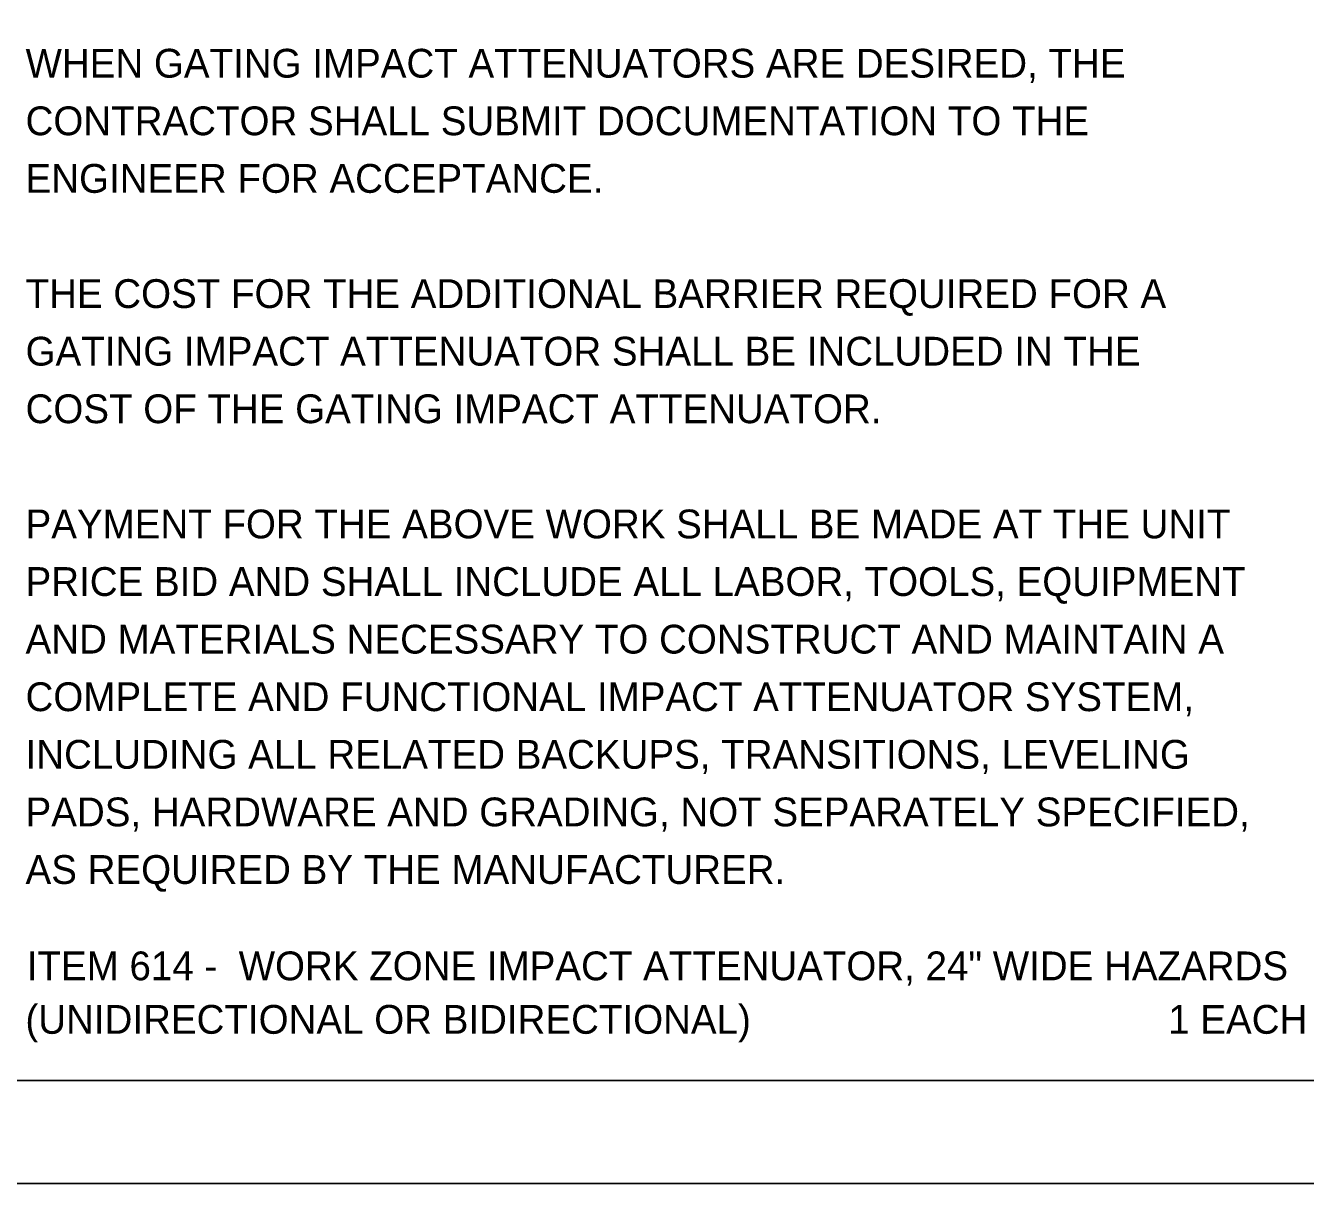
# Model space of a CAD drawing. Extents: x 0 to 34, y 0 to 22.
# Drawn here: x 24.66 to 30.88, y 0 to 5.63 of the extents above; entities that cross this region are included whole.
import ezdxf

# ---------------------------------------------------------------- set-up
doc = ezdxf.new("R2010")
doc.units = 0
for name, color, linetype in [('SH_Border', 7, 'Continuous'), ('SH_Cut_Line', 7, 'Continuous'), ('SH_Text', 7, 'Continuous')]:
    doc.layers.add(name, color=color, linetype=linetype)

msp = doc.modelspace()

# ---------------------------------------------------------------- linework, layer by layer
at = {"layer": 'SH_Border'}
msp.add_lwpolyline([(1.5, 21.5), (33.5, 21.5), (33.5, 0.5), (1.5, 0.5)], close=True, dxfattribs=at)
at = {"layer": 'SH_Cut_Line'}
msp.add_lwpolyline([(0, 0), (34, 0), (34, 22), (0, 22)], close=True, dxfattribs=at)

# ---------------------------------------------------------------- texts
at = {"layer": 'SH_Text'}
for s, p in [('WHEN GATING IMPACT ATTENUATORS ARE DESIRED, THE', (24.66, 5.3761)), ('CONTRACTOR SHALL SUBMIT DOCUMENTATION TO THE', (24.66, 5.0961)), ('ENGINEER FOR ACCEPTANCE.', (24.66, 4.8161)), ('THE COST FOR THE ADDITIONAL BARRIER REQUIRED FOR A', (24.66, 4.2561)), ('GATING IMPACT ATTENUATOR SHALL BE INCLUDED IN THE', (24.66, 3.9761)), ('COST OF THE GATING IMPACT ATTENUATOR.', (24.66, 3.6961)), ('PAYMENT FOR THE ABOVE WORK SHALL BE MADE AT THE UNIT', (24.66, 3.1361)), ('PRICE BID AND SHALL INCLUDE ALL LABOR, TOOLS, EQUIPMENT', (24.66, 2.8561)), ('AND MATERIALS NECESSARY TO CONSTRUCT AND MAINTAIN A', (24.66, 2.5761)), ('COMPLETE AND FUNCTIONAL IMPACT ATTENUATOR SYSTEM,', (24.66, 2.2961)), ('INCLUDING ALL RELATED BACKUPS, TRANSITIONS, LEVELING', (24.66, 2.0161)), ('PADS, HARDWARE AND GRADING, NOT SEPARATELY SPECIFIED,', (24.66, 1.7361)), ('AS REQUIRED BY THE MANUFACTURER.', (24.66, 1.4561)), ('ITEM 614 -  WORK ZONE IMPACT ATTENUATOR, 24" WIDE HAZARDS', (24.6659, 0.9876)), ('(UNIDIRECTIONAL OR BIDIRECTIONAL)                                       1 EACH', (24.6593, 0.7275))]:
    msp.add_text(s, height=0.14, dxfattribs=at).set_placement(p)

doc.saveas('drawing.dxf')
